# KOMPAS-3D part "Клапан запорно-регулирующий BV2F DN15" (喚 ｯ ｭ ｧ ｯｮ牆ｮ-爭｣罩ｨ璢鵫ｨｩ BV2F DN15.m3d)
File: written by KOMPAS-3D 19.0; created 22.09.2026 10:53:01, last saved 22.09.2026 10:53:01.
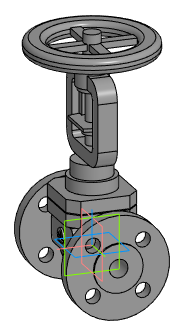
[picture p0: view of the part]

Document properties: Автор: Энергия; Полное имя файла: Z:\3.Личные\sachek\Dendor\_3D для проектировщиков\5.7 Клапан запорно-регулирующий BV2F\BV2F_STP\Клапан запорно-регулирующий BV2F DN15.m3d

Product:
- Part/product: Клапан запорно-регулирующий BV2F DN15

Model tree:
1. Операция без истории:1  (labels: Клапан запорно-регулирующий BV2F DN15)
